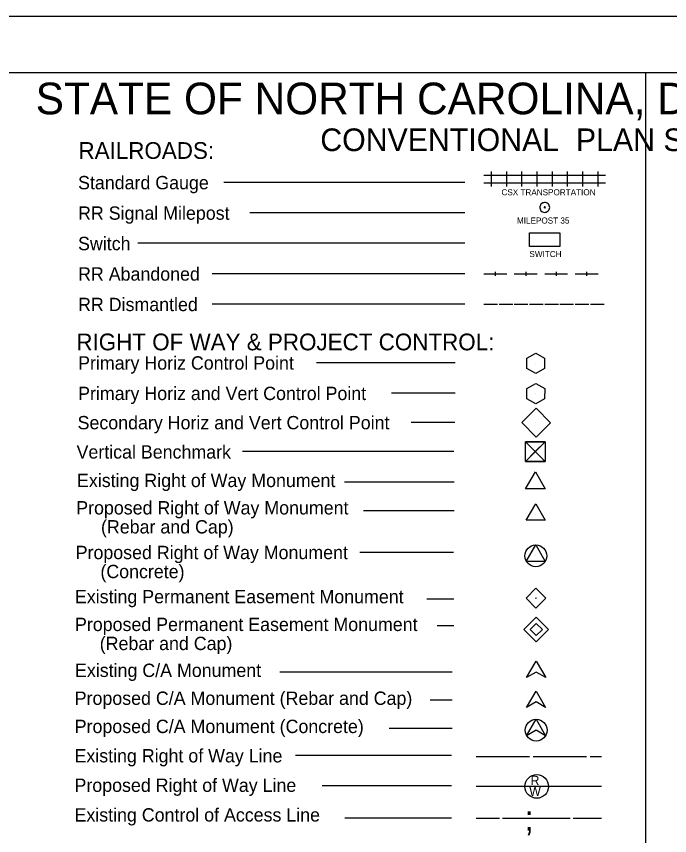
# Model space of a CAD drawing. Extents: x 1855058 to 1858918, y 1540202 to 1542502.
# Drawn here: x 1857552 to 1857985, y 1541959 to 1542502 of the extents above; entities that cross this region are included whole.
import ezdxf

# ---------------------------------------------------------------- set-up
doc = ezdxf.new("R2010")
doc.units = 0
for name, color, linetype in [('CTL Vertical Benchmark CELL', 7, 'Continuous'), ('Default', 7, 'Continuous'), ('Exist Contamination Potential Cell', 7, 'Continuous'), ('Sheet Data Field CELL', 7, 'Continuous'), ('Sheet Symbology CELL', 7, 'Continuous')]:
    doc.layers.add(name, color=color, linetype=linetype)

msp = doc.modelspace()

# ---------------------------------------------------------------- linework, layer by layer
at = {"layer": 'CTL Vertical Benchmark CELL'}
msp.add_line((1857896.09, 1542095.51), (1857896.09, 1542095.51), dxfattribs=at)
for points in [[(1857896.09, 1542103.63), (1857904.21, 1542095.51), (1857896.09, 1542087.39), (1857887.96, 1542095.51)], [(1857896.09, 1542099.57), (1857900.15, 1542095.51), (1857896.09, 1542091.45), (1857892.02, 1542095.51)]]:
    msp.add_lwpolyline(points, close=True, dxfattribs=at)
at = {"layer": 'Default'}
msp.add_lwpolyline([(1857118.6, 1542501.77), (1857118.6, 1541401.77), (1858818.6, 1541401.77), (1858818.6, 1542501.77)], close=True, dxfattribs=at)
at = {"layer": 'Exist Contamination Potential Cell'}
for p, q in [((1858818.6, 1542501.77), (1857118.6, 1542501.77)), ((1857968.6, 1542464.27), (1857968.58, 1541439.27))]:
    msp.add_line(p, q, dxfattribs=at)
at = {"layer": 'Sheet Data Field CELL'}
for p, q in [((1857866.42, 1542389.01), (1857866.42, 1542399.1)), ((1857876.51, 1542389.01), (1857876.51, 1542399.1)), ((1857886.6, 1542389.01), (1857886.6, 1542399.1)), ((1857896.69, 1542389.01), (1857896.69, 1542399.1)), ((1857906.78, 1542389.01), (1857906.78, 1542399.1)), ((1857916.87, 1542389.01), (1857916.87, 1542399.1)), ((1857926.96, 1542389.01), (1857926.96, 1542399.1)), ((1857937.05, 1542389.01), (1857937.05, 1542399.1)), ((1857861.38, 1542396.57), (1857871.47, 1542396.57)), ((1857871.47, 1542396.57), (1857881.56, 1542396.57)), ((1857881.56, 1542396.57), (1857891.65, 1542396.57)), ((1857891.65, 1542396.57), (1857901.74, 1542396.57)), ((1857901.74, 1542396.57), (1857911.83, 1542396.57)), ((1857911.83, 1542396.57), (1857921.92, 1542396.57)), ((1857921.92, 1542396.57), (1857932.01, 1542396.57)), ((1857932.01, 1542396.57), (1857942.09, 1542396.57)), ((1857848.88, 1542391.77), (1857689.05, 1542391.77)), ((1857861.38, 1542391.53), (1857871.47, 1542391.53)), ((1857871.47, 1542391.53), (1857881.56, 1542391.53)), ((1857881.56, 1542391.53), (1857891.65, 1542391.53)), ((1857891.65, 1542391.53), (1857901.74, 1542391.53)), ((1857901.74, 1542391.53), (1857911.83, 1542391.53)), ((1857911.83, 1542391.53), (1857921.92, 1542391.53)), ((1857921.92, 1542391.53), (1857932.01, 1542391.53)), ((1857932.01, 1542391.53), (1857942.09, 1542391.53)), ((1857848.88, 1542371.59), (1857706.34, 1542371.59)), ((1857848.88, 1542351.41), (1857632.04, 1542351.41)), ((1857868.95, 1542332.49), (1857868.95, 1542329.97)), ((1857889.13, 1542332.49), (1857889.13, 1542329.97)), ((1857909.3, 1542332.49), (1857909.3, 1542329.97)), ((1857929.48, 1542332.49), (1857929.48, 1542329.97)), ((1857848.88, 1542331.23), (1857681.23, 1542331.23)), ((1857861.38, 1542331.23), (1857876.51, 1542331.23)), ((1857881.56, 1542331.23), (1857896.69, 1542331.23)), ((1857901.74, 1542331.23), (1857916.87, 1542331.23)), ((1857921.92, 1542331.23), (1857937.05, 1542331.23)), ((1857848.88, 1542311.05), (1857681.23, 1542311.05)), ((1857848.88, 1542311.05), (1857681.23, 1542311.05)), ((1857861.38, 1542311.05), (1857870.46, 1542311.05)), ((1857871.47, 1542311.05), (1857880.55, 1542311.05)), ((1857881.56, 1542311.05), (1857890.64, 1542311.05)), ((1857891.65, 1542311.05), (1857900.73, 1542311.05)), ((1857901.74, 1542311.05), (1857910.82, 1542311.05)), ((1857911.83, 1542311.05), (1857920.91, 1542311.05)), ((1857921.92, 1542311.05), (1857931, 1542311.05)), ((1857932.01, 1542311.05), (1857941.09, 1542311.05)), ((1857842.41, 1542272.32), (1857750.57, 1542272.32)), ((1857895.82, 1542271.94), (1857895.82, 1542271.94)), ((1857842.41, 1542252.14), (1857800.12, 1542252.14)), ((1857895.81, 1542251.8), (1857895.81, 1542251.8)), ((1857842.09, 1542232.76), (1857813.29, 1542232.76)), ((1857895.94, 1542232.55), (1857895.94, 1542232.55)), ((1857841.4, 1542213.37), (1857701.32, 1542213.37)), ((1857895.44, 1542213.38), (1857895.44, 1542213.38)), ((1857841.71, 1542193.21), (1857769.02, 1542193.21)), ((1857841.81, 1542174.26), (1857781.55, 1542174.26)), ((1857895.81, 1542171.62), (1857895.81, 1542171.62)), ((1857841.31, 1542146.61), (1857779.27, 1542146.61)), ((1857895.83, 1542144.32), (1857895.83, 1542144.32)), ((1857841.39, 1542115.64), (1857823.68, 1542115.64)), ((1857895.91, 1542116.3), (1857895.91, 1542116.3)), ((1857841.39, 1542097.86), (1857830.49, 1542097.86)), ((1857889.76, 1542063.65), (1857896.07, 1542074.55)), ((1857896.07, 1542074.55), (1857902.37, 1542063.65)), ((1857840.39, 1542067.37), (1857726.14, 1542067.37)), ((1857896.07, 1542067.29), (1857889.76, 1542063.65)), ((1857902.37, 1542063.65), (1857896.07, 1542067.29)), ((1857889.73, 1542043.87), (1857896.03, 1542054.76)), ((1857896.03, 1542054.76), (1857902.34, 1542043.87)), ((1857840.49, 1542048.68), (1857825.79, 1542048.68)), ((1857896.03, 1542047.5), (1857889.73, 1542043.87)), ((1857902.34, 1542043.87), (1857896.03, 1542047.5)), ((1857889.73, 1542025.19), (1857896.03, 1542036.09)), ((1857896.03, 1542036.09), (1857902.34, 1542025.19)), ((1857840.49, 1542030), (1857798.72, 1542030)), ((1857896.03, 1542028.83), (1857889.73, 1542025.19)), ((1857902.34, 1542025.19), (1857896.03, 1542028.83)), ((1857840.04, 1542012.07), (1857736.61, 1542012.07)), ((1857856.22, 1542011.49), (1857891.53, 1542011.49)), ((1857894.05, 1542011.49), (1857929.36, 1542011.49)), ((1857931.89, 1542011.49), (1857939.45, 1542011.49)), ((1857840.04, 1541991.89), (1857754.24, 1541991.89)), ((1857856.22, 1541991.76), (1857939.45, 1541991.76)), ((1857840.04, 1541970.57), (1857769.17, 1541970.57)), ((1857856.22, 1541970.57), (1857871.82, 1541970.57)), ((1857873.83, 1541970.57), (1857918.64, 1541970.57)), ((1857920.66, 1541970.57), (1857939.45, 1541970.57))]:
    msp.add_line(p, q, dxfattribs=at)
for points in [[(1857905.03, 1542375.18), (1857904.96, 1542375.84), (1857904.77, 1542376.49), (1857904.44, 1542377.08), (1857903.98, 1542377.54), (1857903.45, 1542377.93), (1857902.86, 1542378.26), (1857902.27, 1542378.39), (1857901.55, 1542378.46), (1857900.9, 1542378.33), (1857900.31, 1542378.13), (1857899.72, 1542377.8), (1857899.26, 1542377.34), (1857898.87, 1542376.75), (1857898.6, 1542376.16), (1857898.47, 1542375.51), (1857898.47, 1542374.85), (1857898.6, 1542374.2), (1857898.87, 1542373.61), (1857899.26, 1542373.02), (1857899.72, 1542372.56), (1857900.31, 1542372.23), (1857900.9, 1542372.04), (1857901.55, 1542371.9), (1857902.27, 1542371.97), (1857902.86, 1542372.1), (1857903.45, 1542372.43), (1857903.98, 1542372.82), (1857904.44, 1542373.28), (1857904.77, 1542373.87), (1857904.96, 1542374.53), (1857905.03, 1542375.18)], [(1857901.88, 1542375.57), (1857901.68, 1542375.57), (1857901.49, 1542375.44), (1857901.36, 1542375.25), (1857901.42, 1542375.05), (1857901.55, 1542374.85), (1857901.75, 1542374.79), (1857901.95, 1542374.85), (1857902.08, 1542374.98), (1857902.14, 1542375.25), (1857902.08, 1542375.44), (1857901.88, 1542375.57)], [(1857895.82, 1542265.23), (1857889.97, 1542268.55), (1857889.97, 1542275.27), (1857895.82, 1542278.66), (1857901.66, 1542275.33), (1857901.66, 1542268.55), (1857895.82, 1542265.23)], [(1857901.97, 1542219.91), (1857888.88, 1542206.83), (1857895.43, 1542213.37), (1857901.97, 1542206.83), (1857888.88, 1542219.91)], [(1857895.43, 1542213.37), (1857901.97, 1542219.91), (1857888.88, 1542219.91), (1857895.43, 1542213.37)], [(1857895.43, 1542213.37), (1857888.88, 1542206.83), (1857901.97, 1542206.83), (1857895.43, 1542213.37)], [(1857888.99, 1542188.71), (1857895.54, 1542200.09), (1857902.09, 1542188.71), (1857888.99, 1542188.71)]]:
    msp.add_lwpolyline(points, dxfattribs=at)
for points in [[(1857891.65, 1542358.44), (1857911.83, 1542358.44), (1857911.83, 1542349.25), (1857891.65, 1542349.25)], [(1857889.92, 1542255.2), (1857895.84, 1542258.5), (1857901.76, 1542255.25), (1857901.67, 1542248.47), (1857895.75, 1542245.03), (1857889.92, 1542248.33)], [(1857886.45, 1542232.58), (1857895.99, 1542242.13), (1857905.55, 1542232.57), (1857896.01, 1542223.03)], [(1857888.88, 1542219.91), (1857901.97, 1542219.91), (1857901.97, 1542206.83), (1857888.88, 1542206.83)], [(1857889.5, 1542167.99), (1857895.81, 1542178.88), (1857902.12, 1542167.99)], [(1857889.52, 1542140.68), (1857895.83, 1542151.58), (1857902.13, 1542140.68)], [(1857889.35, 1542116.3), (1857895.91, 1542122.86), (1857902.46, 1542116.3), (1857895.91, 1542109.75)]]:
    msp.add_lwpolyline(points, close=True, dxfattribs=at)
for centre, radius in [((1857895.82, 1542144.31), 7.26), ((1857895.91, 1542116.3), 0.127), ((1857896.03, 1542028.83), 7.26), ((1857896.43, 1541991.55), 7.82)]:
    msp.add_circle(centre, radius, dxfattribs=at)
at = {"layer": 'Sheet Symbology CELL'}
msp.add_line((1858781.1, 1542464.27), (1857156.1, 1542464.27), dxfattribs=at)

# ---------------------------------------------------------------- texts
at = {"layer": 'Sheet Data Field CELL'}
for s, height, p in [('STATE OF NORTH CAROLINA, DIVISION OF HIGHWAYS', 21, (1857564.35, 1542436.88)), ('CONVENTIONAL  PLAN SHEET SYMBOLS', 15, (1857752.99, 1542412.51)), ('RAILROADS:', 11.098, (1857592.72, 1542407.36)), ('Standard Gauge', 8.8282, (1857592.44, 1542387.2)), ('CSX TRANSPORTATION', 4.0357, (1857873.05, 1542383.22)), ('RR Signal Milepost', 8.8282, (1857592.44, 1542367.02)), ('MILEPOST 35', 4.0357, (1857883.32, 1542364.48)), ('Switch', 8.828, (1857592.44, 1542346.85)), ('SWITCH', 4.036, (1857891.6, 1542342.28)), ('RR Abandoned', 8.8282, (1857592.44, 1542326.67)), ('RR Dismantled', 8.8282, (1857592.44, 1542306.49)), ('RIGHT OF WAY & PROJECT CONTROL:', 11.0983, (1857591.3, 1542280.51)), ('Primary Horiz Control Point', 8.8282, (1857592.45, 1542267.73)), ('Primary Horiz and Vert Control Point', 8.8282, (1857592.45, 1542247.55)), ('Secondary Horiz and Vert Control Point', 8.8282, (1857592.13, 1542228.17)), ('Vertical Benchmark', 8.8282, (1857591.43, 1542208.78)), ('Existing Right of Way Monument', 8.8282, (1857591.75, 1542189.9)), ('Proposed Right of Way Monument', 8.8282, (1857591.23, 1542171.76)), ('     (Rebar and Cap)', 8.8282, (1857591.23, 1542159.15)), ('Proposed Right of Way Monument', 8.8282, (1857590.85, 1542142.15)), ('     (Concrete)', 8.8282, (1857590.85, 1542129.54)), ('Existing Permanent Easement Monument', 8.8282, (1857590.36, 1542112.9)), ('Proposed Permanent Easement Monument', 8.8282, (1857590.4, 1542094.51)), ('     (Rebar and Cap)', 8.8282, (1857590.4, 1542081.89)), ('Existing C/A Monument', 8.8282, (1857590.42, 1542064.07)), ('Proposed C/A Monument (Rebar and Cap)', 8.8282, (1857590.21, 1542045.59)), ('Proposed C/A Monument (Concrete)', 8.8282, (1857590.21, 1542026.92)), ('Existing Right of Way Line', 8.8282, (1857590.08, 1542007.47)), ('Proposed Right of Way Line', 8.8282, (1857590.08, 1541987.93)), ('R', 6.13, (1857892.32, 1541992.47)), ('W', 6.13, (1857891.45, 1541985.25)), ('Existing Control of Access Line', 8.8282, (1857590.08, 1541968.29)), (';', 16.65, (1857888.29, 1541962.31))]:
    msp.add_text(s, height=height, dxfattribs=at).set_placement(p)

doc.saveas('drawing.dxf')
